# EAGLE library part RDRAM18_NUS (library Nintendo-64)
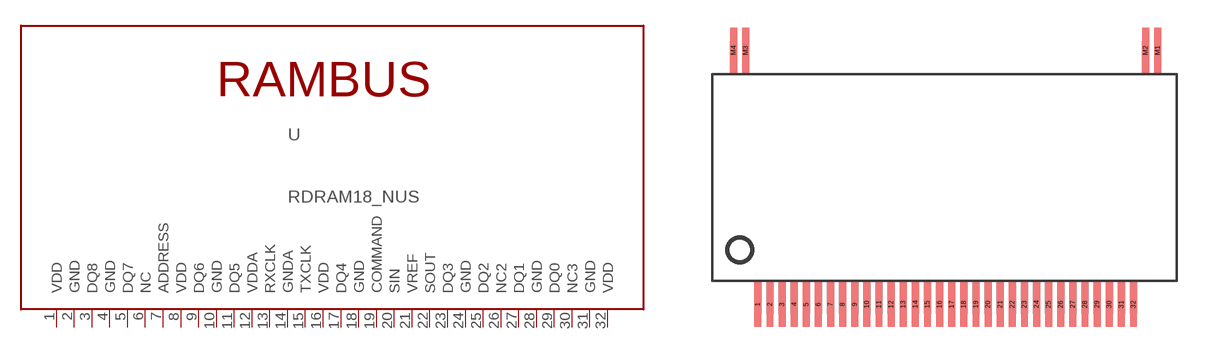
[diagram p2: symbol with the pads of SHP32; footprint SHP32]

Designator prefix -

## RDRAM18_NUS  [SHP32]
1  VDD
2  GND
3  DQ8
4  GND
5  DQ7
6  NC
7  ADDRESS
8  VDD
9  DQ6
10  GND
11  DQ5
12  VDDA
13  RXCLK
14  GNDA
15  TXCLK
16  VDD
17  DQ4
18  GND
19  COMMAND
20  SIN
21  VREF
22  SOUT
23  DQ3
24  GND
25  DQ2
26  NC2
27  DQ1
28  GND
29  DQ0
30  NC3
31  GND
32  VDD

## Footprint SHP32 (pad centres in mm)
smd 0.37 x 2.4: 1 -10.075,-5.951; 2 -9.425,-5.951; 3 -8.775,-5.951; 4 -8.125,-5.951; 5 -7.475,-5.951; 6 -6.825,-5.951; 7 -6.175,-5.951; 8 -5.525,-5.951; 9 -4.875,-5.951; 10 -4.225,-5.951; 11 -3.575,-5.951; 12 -2.925,-5.951; 13 -2.275,-5.951; 14 -1.625,-5.951; 15 -0.975,-5.951; 16 -0.325,-5.951; 17 0.325,-5.951; 18 0.975,-5.951; 19 1.625,-5.951; 20 2.275,-5.951; 21 2.925,-5.951; 22 3.575,-5.951; 23 4.225,-5.951; 24 4.875,-5.951; 25 5.525,-5.951; 26 6.175,-5.951; 27 6.825,-5.951; 28 7.475,-5.951; 29 8.125,-5.951; 30 8.775,-5.951; 31 9.425,-5.951; 32 10.075,-5.951; M1 11.375,7.699; M2 10.725,7.699; M3 -10.725,7.699; M4 -11.375,7.699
